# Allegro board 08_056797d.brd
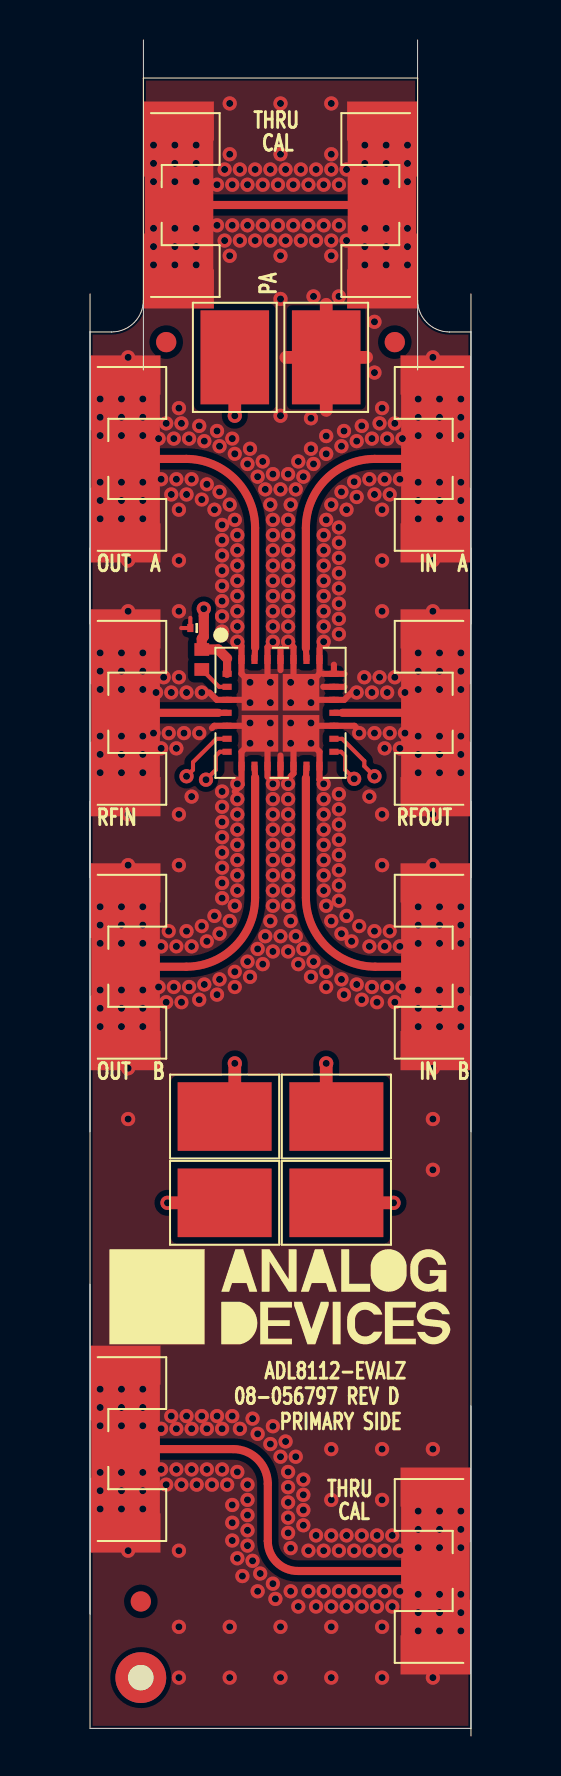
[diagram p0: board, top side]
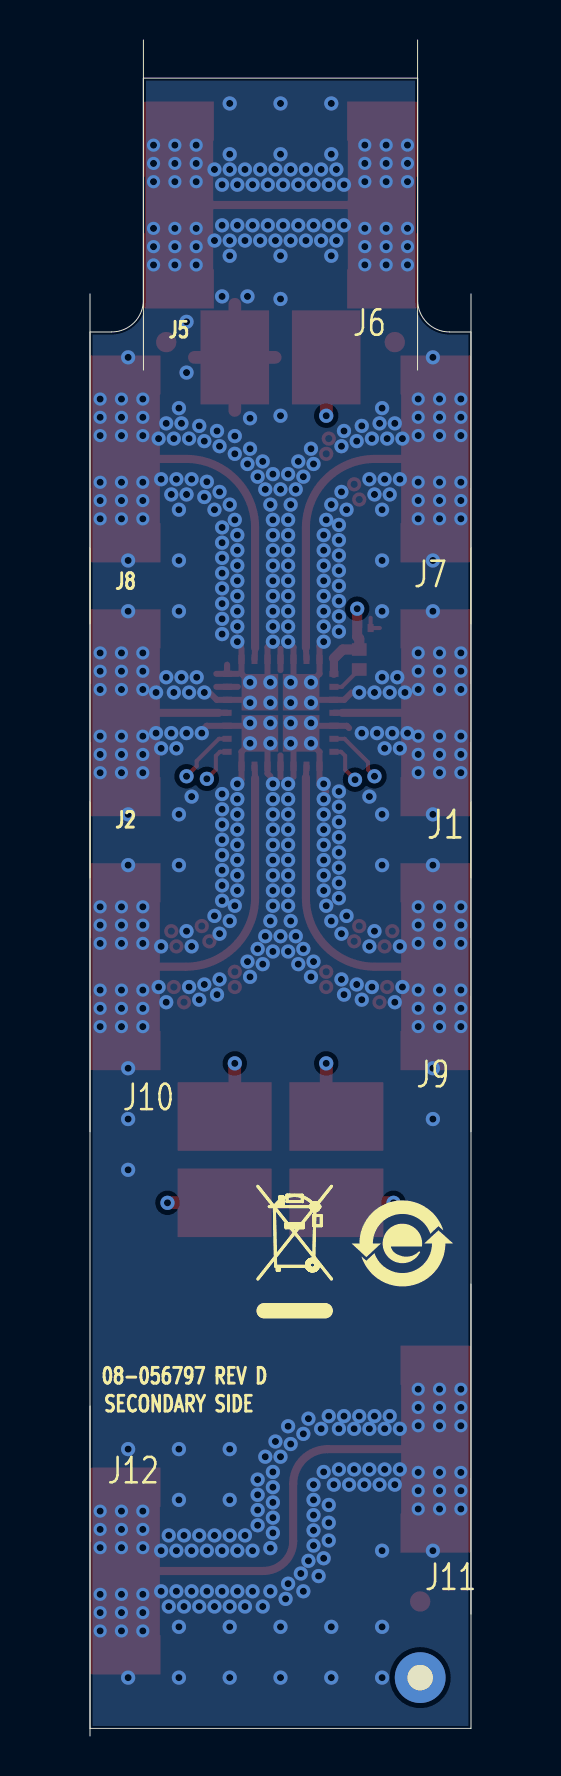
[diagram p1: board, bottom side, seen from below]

Outline 19.05 x 84.84 mm; copper layers: TOP, L2_GND, L3_GND, BOTTOM. Coordinates in mm from the lower left corner of the outline.
Outline path: 0,70.23 1.08,70.23 arc(2.2,70.7) 2.67,71.82 2.67,82.93 16.38,82.93 16.38,71.82 arc(16.85,70.7) 17.97,70.23 19.05,70.23 19.05,0.38 0,0.38 0,70.23

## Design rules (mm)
constraint set DEFAULT: min track width 0.203

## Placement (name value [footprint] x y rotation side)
C1  10pF  [C0201]  5.33 55.42 0 top
GND  5016  [CNKEY5016TP]  11.81 68.96 270 top
J1  25-146-1000-92  [CNK38G62THK_EDGE]  0 51.18 180 top
J2  25-146-1000-92  [CNK38G62THK_EDGE]  19.05 51.18 0 top
J5  25-146-1000-92  [CNK38G62THK_EDGE]  16.38 76.58 0 top
J6  25-146-1000-92  [CNK38G62THK_EDGE]  2.67 76.58 180 top
J7  25-146-1000-92  [CNK38G62THK_EDGE]  0 63.88 180 top
J8  25-146-1000-92  [CNK38G62THK_EDGE]  19.05 63.88 0 top
J9  25-146-1000-92  [CNK38G62THK_EDGE]  0 38.48 180 top
J10  25-146-1000-92  [CNK38G62THK_EDGE]  19.05 38.48 0 top
J11  25-146-1000-92  [CNK38G62THK_EDGE]  0 14.35 180 top
J12  25-146-1000-92  [CNK38G62THK_EDGE]  19.05 8.26 0 top
NOREF  -  []  0 0.38 0 top
NOREF#2  -  []  0 70.23 0 top
NOREF#3  -  []  19.05 0.38 90 top
NOREF#4  -  []  -148.69 242.57 0 top
NOREF#5  -  []  2.54 2.92 0 top
NOREF#6  -  []  16.38 82.93 0 top
NOREF#7  -  []  0 0.38 0 top
NOREF#8  -  []  9.53 21.97 0 top
NOREF#9  -  []  -226.7 -178.69 0 top
NOREF#10  -  []  0 70.23 0 top
NOREF#11  -  []  10.03 101.47 0 top
NOREF#12  -  []  2.67 82.93 270 top
NOREF#13  -  []  -104.65 -130.43 0 top
NOREF#14  -  []  16.38 82.93 180 top
NOREF#15  -  []  2.67 82.93 0 top
NOREF#16  -  []  0 51.18 0 top
NOREF#17  -  []  -229.87 -181.99 0 top
NOREF#18  -  []  19.05 0.38 0 top
NOREF#19  -  []  2.67 82.93 0 top
NOREF#20  -  [unnamed#2]  3.81 69.72 0 top
NOREF#21  -  []  19.05 0.38 90 top
NOREF#22  -  []  -88.9 -63.88 0 top
NOREF#23  -  []  0 0.38 0 top
NOREF#24  -  []  116.33 298.2 0 top
NOREF#25  -  []  -183.52 -64.13 0 top
NOREF#26  -  []  2.24 70.74 0 top
NOREF#27  -  []  19.05 0.38 90 top
NOREF#28  -  [unnamed#2]  15.24 69.72 0 top
NOREF#29  -  [unnamed#2]  2.54 2.92 0 top
NOREF#30  -  [unnamed#2]  2.54 6.73 0 top
NOREF#31  -  []  132.97 -25.02 0 top
NOREF#32  -  []  -2.29 167.26 0 top
NOREF#33  -  []  2.54 2.92 0 top
NOREF#34  -  []  9.02 20.95 180 bottom
NOREF#35  -  []  3.43 24.64 180 bottom
NOREF#36  -  []  9.53 57.15 90 bottom
R1  332  [R0402]  5.59 53.85 270 top
U1  ADL8112ACCZ  [LGA28_6X6_4PAD1_83X1_83]  9.53 51.18 270 top
VA  5016  [CNKEY5016TP]  6.73 26.67 0 top
VB  5016  [CNKEY5016TP]  6.73 30.99 0 top
VDD  5016  [CNKEY5016TP]  7.24 68.96 90 top
VDD_SW  5016  [CNKEY5016TP]  12.32 26.67 0 top
VSS  5016  [CNKEY5016TP]  12.32 30.99 0 top

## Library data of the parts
C1 = CAP: Tolerance: 5; User Part Number: UPN; alternate symbols: (C0201NC,C0201L); part number: CAP_SM-10PF,25V,5,E022849,C0201; tolerance: 5
GND VA VB VDD VDD_SW VSS = CNTP1P: Tolerance: N/A; User Part Number: UPN; alternate symbols: (); part number: CNTP1P_SM-5016,E005890,CNKEY5016TP; tolerance: N/A
J1 J2 J5-J12 = CNBNC4P: Tolerance: N/A; User Part Number: UPN; alternate symbols: (CNK38G62THK_EDGE_ADL81XX,CNK38G62THK_EDGE_HMC84X3,CNK40G62THK-SRI-SW_EDGE,CNK38G62THK_EDGE_ADMV1014); part number: CNBNC4P_SM-25-146-1000-92,E023346,CNK38G62THK_EDGE; tolerance: N/A
R1 = RES: User Part Number: UPN; Tolerance: 1; alternate symbols: (R0402L); part number: RES_SM-332,E056721,1/16W,1,R0402; tolerance: 1
U1 = ADL811X: User Part Number: UPN; Tolerance: N/A; alternate symbols: (); part number: ADL811X_SM-ADL8112ACCZ,E060217,LGA28_6X6_4PAD1_83X1_83; tolerance: N/A

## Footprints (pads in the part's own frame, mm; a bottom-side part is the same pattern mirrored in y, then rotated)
C0201
  rect 0.305x0.406 smd: 1(-0.318,0) 2(0.318,0)
CNK38G62THK_EDGE
  custom 0.102x0.102 smd: 1(-1.549,0)
  custom 0.873x0.873 smd: 2(-1.778,-3.302) 3(-1.778,3.302)
  rect 3.429x8.56 smd: 4(-1.778,0)
CNKEY5016TP
  rect 4.699x3.429 smd: 1(0,0)
LGA28_6X6_4PAD1_83X1_83
  rect 0.305x0.457 smd: 1(-1.95,-2.671) 2(-1.3,-2.671) 3(-0.65,-2.671) 4(0,-2.671) 5(0.65,-2.671) 6(1.3,-2.671) 7(1.95,-2.671) 15(1.95,2.671) 16(1.3,2.671) 17(0.65,2.671) 18(0,2.671) 19(-0.65,2.671) 20(-1.3,2.671) 21(-1.95,2.671)
  rect 0.457x0.305 smd: 8(2.671,-1.95) 9(2.671,-1.3) 10(2.671,-0.65) 11(2.671,0) 12(2.671,0.65) 13(2.671,1.3) 14(2.671,1.95) 22(-2.671,1.95) 23(-2.671,1.3) 24(-2.671,0.65) 25(-2.671,0) 26(-2.671,-0.65) 27(-2.671,-1.3) 28(-2.671,-1.95)
  rect 1.829x1.829 smd: PAD1(-1.028,-1.028) PAD2(1.028,-1.028) PAD3(1.028,1.028) PAD4(-1.028,1.028)
R0402
  rect 0.635x0.737 smd: 1(-0.5,0) 2(0.5,0)
unnamed#2
  round 1.016 smd: (0,0)

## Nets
GND: C1.1 GND.1(N1) J1.2 J1.3 J1.4(SH3) J2.2 J2.3 J2.4(SH3) J5.2 J5.3 J5.4(SH3) J6.2 J6.3 J6.4(SH3) J7.2 J7.3 J7.4(SH3) J8.2 J8.3 J8.4(SH3) J9.2 J9.3 J9.4(SH3) J10.2 J10.3 J10.4(SH3) J11.2 J11.3 J11.4(SH3) J12.2 J12.3 J12.4(SH3) U1.3 U1.5 U1.8 U1.10 U1.11 U1.12 U1.14 U1.17 U1.19 U1.20 U1.21 U1.22 U1.24 U1.25 U1.26 U1.28 U1.PAD1 U1.PAD2 U1.PAD3 U1.PAD4
VDD_PA: C1.2(N2) R1.1 U1.1 VDD.1(N1)
VDD_SW: U1.16 VDD_SW.1(N1)
VSS_SW: U1.15(VSS2) VSS.1(N1)
IN_A: J8.1 U1.23
IN_B: J10.1 U1.13
OUT_A: J7.1 U1.27
OUT_B: J9.1 U1.9
OUT_IN_B_THRU-CAL: J11.1 J12.1
RFIN: J1.1 U1.4
RFOUT: J2.1 U1.18
THRU-CAL: J5.1 J6.1
UNNAMED_4_ADL811X_I101_RBIAS: R1.2(N2) U1.2
VA: U1.6 VA.1(N1)
VB: U1.7 VB.1(N1)

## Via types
v1: diameter 0.711, hole 0.356, TOP to BOTTOM, 430 vias
v2: diameter 0.66, hole 0.356, TOP to BOTTOM, 180 vias
v3: diameter 0.711, hole 0.356, TOP to L2_GND, 20 vias

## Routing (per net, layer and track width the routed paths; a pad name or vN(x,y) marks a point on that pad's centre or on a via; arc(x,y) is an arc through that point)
GND: length 49.4
  TOP w0.203: 5.02,55.93 C1.1 4.56,55.42 ; 12.71,51.83 12.73,51.83
  TOP w0.254: 11.47,54.39 11.47,54.53 v1(11.68,54.74)
  TOP w0.305: v1(11.68,47.62) 11.47,47.83 U1.14 11.47,49.23 v1(11.05,49.66) U1.PAD3 ; U1.PAD4 10.93,51.83 U1.19 12.71,51.83 13.08,52.2 ; U1.PAD4 v1(11.05,52.7) 11.47,53.13 U1.22 11.47,54.39 ; U1.PAD4 10.17,52.59 U1.24 10.17,54.47 v1(9.91,54.74) ; U1.PAD1 8.88,52.59 U1.26 8.88,54.47 v1(9.14,54.74) ; U1.PAD1 8.12,51.83 U1.3 6.34,51.83 5.97,52.2 ; U1.PAD1 v1(8,52.7) 7.58,53.13 U1.28 7.58,54.53 v1(7.37,54.74) ; 13.59,50.16 13.22,50.53 U1.17 10.93,50.53 U1.PAD3 ; 6.1,50.42 6.21,50.53 U1.5 8.12,50.53 U1.PAD2 ; 8.88,47.98 U1.10 8.88,49.77 U1.PAD2 ; 9.53,53.32 U1.25 9.53,54.39 ; 9.53,49.04 U1.11 9.53,47.98 ; 12.73,52.48 U1.20 11.66,52.48 ; U1.21 12.2,53.59 ; U1.21 12.73,53.13 ; U1.21 11.66,53.13 ; U1.PAD2 v1(8,49.66) 7.58,49.23 U1.8 7.58,47.58 7.24,47.24 ; U1.PAD3 10.17,49.77 U1.12 10.17,48.15 10.03,48.01
  TOP w0.635: GND.1 11.81,71.62 ; GND.1 13.83,68.96 ; GND.1 11.81,66.31 ; GND.1 9.79,68.96
  vias: v1(1.91,68.96) v1(1.91,58.8) v1(1.91,56.26) v1(1.91,46.1) v1(1.91,43.56) v1(1.91,33.4) v1(1.91,30.86) v1(1.91,9.27) v1(3.18,50.16) v1(3.3,52.2) v1(3.43,64.9) v1(3.43,37.46) v1(3.56,62.87) v1(3.56,49.4) v1(3.56,39.5) v1(3.56,15.37) v1(3.56,13.34) v1(3.68,52.96) v1(3.81,65.66) v1(3.81,36.7) v1(3.81,12.57) v1(3.94,50.16) v1(4.06,62.1) v1(4.06,52.2) v1(4.06,16) v1(4.19,64.9) v1(4.32,62.87) v1(4.32,49.4) v1(4.32,15.37) v1(4.32,13.34) v1(4.45,66.42) v1(4.45,61.34) v1(4.45,58.8) v1(4.45,56.26) v1(4.45,52.96) v1(4.45,46.1) v1(4.45,43.56) v1(4.45,9.27) v1(4.45,5.46) v1(4.45,2.92) v1(4.57,65.66) v1(4.57,12.57) v1(4.7,50.16) v1(4.83,62.1) v1(4.83,52.2) v1(4.83,40.26) v1(4.83,16) v1(4.95,64.9) v1(4.95,37.46) v1(5.08,62.87) v1(5.08,46.99) v1(5.08,39.5) v1(5.08,15.37) v1(5.08,13.34) v1(5.33,12.57) v1(5.46,65.53) v1(5.46,50.16) v1(5.46,36.83) v1(5.59,52.2) v1(5.59,16) v1(5.72,64.77) v1(5.72,37.59) v1(5.84,15.37) v1(5.84,13.34) v1(6.1,12.57) v1(6.22,61.34) v1(6.22,41.02) v1(6.35,77.6) v1(6.35,75.57) v1(6.35,65.28) v1(6.35,37.08) v1(6.35,16) v1(6.48,64.52) v1(6.48,62.23) v1(6.48,40.13) v1(6.48,37.85) v1(6.6,60.58) v1(6.6,59.82) v1(6.6,59.05) v1(6.6,58.29) v1(6.6,57.53) v1(6.6,56.77) v1(6.6,56.01) v1(6.6,55.24) v1(6.6,47.24) v1(6.6,46.48) v1(6.6,45.72) v1(6.6,44.96) v1(6.6,44.2) v1(6.6,43.43) v1(6.6,42.67) v1(6.6,41.91) v1(6.6,15.37) v1(6.6,13.34) v1(6.73,78.36) v1(6.73,74.8) v1(6.86,12.57) v1(6.99,81.66) v1(6.99,79.12) v1(6.99,74.04) v1(6.99,61.59) v1(6.99,40.77) v1(6.99,5.46) v1(6.99,2.92) v1(7.11,77.6) v1(7.11,75.57) v1(7.11,16) v1(7.11,11.56) v1(7.11,10.67) v1(7.11,9.78) v1(7.24,60.83) v1(7.24,41.53) v1(7.37,60.07) v1(7.37,59.31) v1(7.37,58.55) v1(7.37,57.78) v1(7.37,57.02) v1(7.37,56.26) v1(7.37,55.5) v1(7.37,47.62) v1(7.37,46.86) v1(7.37,46.1) v1(7.37,45.34) v1(7.37,44.58) v1(7.37,43.81) v1(7.37,43.05) v1(7.37,42.29) v1(7.37,13.21) v1(7.37,8.89) v1(7.49,78.36) v1(7.49,74.8) v1(7.49,15.37) v1(7.62,8) v1(7.87,77.6) v1(7.87,75.57) v1(7.87,63.63) v1(7.87,38.73) v1(7.87,12.57) v1(7.87,11.81) v1(7.87,11.05) v1(7.87,10.29) v1(7.87,9.53) v1(8,64.39) v1(8,51.69) v1(8,50.67) v1(8,37.97) v1(8.13,15.88) v1(8.13,8.76) v1(8.26,78.36) v1(8.26,74.8) v1(8.38,62.99) v1(8.38,39.37) v1(8.38,15.11) v1(8.38,7.24) v1(8.51,8.13) v1(8.64,77.6) v1(8.64,75.57) v1(8.64,63.75) v1(8.64,38.61) v1(8.76,62.36) v1(8.76,40.01) v1(9.02,78.36) v1(9.02,74.8) v1(9.02,61.59) v1(9.02,52.7) v1(9.02,51.69) v1(9.02,50.67) v1(9.02,49.66) v1(9.02,40.77) v1(9.02,14.61) v1(9.14,63.12) v1(9.14,60.83) v1(9.14,60.07) v1(9.14,59.31) v1(9.14,58.55) v1(9.14,57.78) v1(9.14,57.02) v1(9.14,56.26) v1(9.14,55.5) v1(9.14,47.62) v1(9.14,46.86) v1(9.14,46.1) v1(9.14,45.34) v1(9.14,44.58) v1(9.14,43.81) v1(9.14,43.05) v1(9.14,42.29) v1(9.14,41.53) v1(9.14,39.24) v1(9.14,15.49) v1(9.14,7.62) v1(9.27,6.86) v1(9.4,77.6) v1(9.4,75.57) v1(9.53,81.66) v1(9.53,79.12) v1(9.53,74.04) v1(9.53,71.88) v1(9.53,66.04) v1(9.53,62.36) v1(9.53,40.01) v1(9.53,13.97) v1(9.53,5.46) v1(9.53,2.92) v1(9.78,78.36) v1(9.78,74.8) v1(9.78,14.73) v1(9.91,63.12) v1(9.91,60.83) v1(9.91,60.07) v1(9.91,59.31) v1(9.91,58.55) v1(9.91,57.78) v1(9.91,57.02) v1(9.91,56.26) v1(9.91,55.5) v1(9.91,47.62) v1(9.91,46.86) v1(9.91,46.1) v1(9.91,45.34) v1(9.91,44.58) v1(9.91,43.81) v1(9.91,43.05) v1(9.91,42.29) v1(9.91,41.53) v1(9.91,39.24) v1(9.91,13.21) v1(9.91,12.45) v1(9.91,11.68) v1(9.91,10.92) v1(9.91,10.16) v1(10.03,61.59) v1(10.03,52.7) v1(10.03,51.69) v1(10.03,50.67) v1(10.03,49.66) v1(10.03,40.77) v1(10.03,9.4) v1(10.03,7.24) v1(10.16,77.6) v1(10.16,75.57) v1(10.29,62.36) v1(10.29,40.01) v1(10.29,13.97) v1(10.41,63.75) v1(10.41,38.61) v1(10.41,6.48) v1(10.54,78.36) v1(10.54,74.8) v1(10.67,62.99) v1(10.67,39.37) v1(10.67,12.83) v1(10.67,12.07) v1(10.67,11.3) v1(10.67,10.54) v1(10.92,77.6) v1(10.92,75.57) v1(10.92,9.27) v1(10.92,7.24) v1(11.05,65.91) v1(11.05,64.39) v1(11.05,51.69) v1(11.05,50.67) v1(11.05,37.97) v1(11.18,72.01) v1(11.18,63.63) v1(11.18,38.73) v1(11.3,78.36) v1(11.3,74.8) v1(11.3,10.03) v1(11.3,6.48) v1(11.68,77.6) v1(11.68,75.57) v1(11.68,60.07) v1(11.68,59.31) v1(11.68,58.55) v1(11.68,57.78) v1(11.68,57.02) v1(11.68,56.26) v1(11.68,55.5) v1(11.68,46.86) v1(11.68,46.1) v1(11.68,45.34) v1(11.68,44.58) v1(11.68,43.81) v1(11.68,43.05) v1(11.68,42.29) v1(11.68,9.27) v1(11.68,7.24) v1(11.81,65.02) v1(11.81,64.14) v1(11.81,60.83) v1(11.81,41.53) v1(12.07,81.66) v1(12.07,79.12) v1(12.07,78.36) v1(12.07,74.8) v1(12.07,74.04) v1(12.07,61.59) v1(12.07,40.77) v1(12.07,14.35) v1(12.07,11.81) v1(12.07,10.03) v1(12.07,6.48) v1(12.07,5.46) v1(12.07,2.92) v1(12.45,77.6) v1(12.45,75.57) v1(12.45,72.01) v1(12.45,60.45) v1(12.45,59.69) v1(12.45,58.93) v1(12.45,58.17) v1(12.45,57.4) v1(12.45,56.64) v1(12.45,55.88) v1(12.45,55.12) v1(12.45,47.12) v1(12.45,46.35) v1(12.45,45.59) v1(12.45,44.83) v1(12.45,44.07) v1(12.45,43.31) v1(12.45,42.55) v1(12.45,41.78) v1(12.45,9.27) v1(12.45,7.24) v1(12.57,64.52) v1(12.57,62.23) v1(12.57,40.13) v1(12.57,37.85) v1(12.7,65.28) v1(12.7,37.08) v1(12.83,78.36) v1(12.83,74.8) v1(12.83,61.34) v1(12.83,41.02) v1(12.83,10.03) v1(12.83,6.48) v1(13.21,62.74) v1(13.21,9.27) v1(13.21,7.24) v1(13.34,64.77) v1(13.34,61.98) v1(13.34,52.2) v1(13.34,37.59) v1(13.46,50.16) v1(13.59,65.53) v1(13.59,36.83) v1(13.59,10.03) v1(13.59,6.48) v1(13.72,52.96) v1(13.97,62.87) v1(13.97,46.99) v1(13.97,39.5) v1(13.97,9.27) v1(13.97,7.24) v1(14.1,64.9) v1(14.1,52.2) v1(14.1,37.46) v1(14.22,70.74) v1(14.22,68.2) v1(14.22,62.1) v1(14.22,50.16) v1(14.22,40.26) v1(14.35,10.03) v1(14.35,6.48) v1(14.48,65.66) v1(14.48,52.96) v1(14.61,66.42) v1(14.61,61.34) v1(14.61,58.8) v1(14.61,56.26) v1(14.61,46.1) v1(14.61,43.56) v1(14.61,14.35) v1(14.61,11.81) v1(14.61,5.46) v1(14.61,2.92) v1(14.73,62.87) v1(14.73,49.4) v1(14.73,9.27) v1(14.73,7.24) v1(14.86,64.9) v1(14.86,52.2) v1(14.99,62.1) v1(14.99,50.16) v1(15.11,10.03) v1(15.11,6.48) v1(15.24,65.66) v1(15.24,52.96) v1(15.24,36.7) v1(15.49,62.87) v1(15.49,49.4) v1(15.49,39.5) v1(15.49,9.27) v1(15.49,7.24) v1(15.62,64.9) v1(15.62,37.46) v1(15.75,52.2) v1(15.75,50.16) v1(17.15,68.96) v1(17.15,58.8) v1(17.15,56.26) v1(17.15,46.1) v1(17.15,43.56) v1(17.15,33.4) v1(17.15,30.86) v1(17.15,28.32) v1(17.15,14.35) v1(17.15,2.92) v2(0.51,66.88) v2(0.51,65.96) v2(0.51,65.05) v2(0.51,62.72) v2(0.51,61.8) v2(0.51,60.89) v2(0.51,54.18) v2(0.51,53.26) v2(0.51,52.35) v2(0.51,50.02) v2(0.51,49.1) v2(0.51,48.19) v2(0.51,41.48) v2(0.51,40.56) v2(0.51,39.65) v2(0.51,37.32) v2(0.51,36.4) v2(0.51,35.49) v2(0.51,17.35) v2(0.51,16.43) v2(0.51,15.52) v2(0.51,13.19) v2(0.51,12.27) v2(0.51,11.36) v2(1.57,66.88) v2(1.57,65.96) v2(1.57,65.05) v2(1.57,62.72) v2(1.57,61.8) v2(1.57,60.89) v2(1.57,54.18) v2(1.57,53.26) v2(1.57,52.35) v2(1.57,50.02) v2(1.57,49.1) v2(1.57,48.19) v2(1.57,41.48) v2(1.57,40.56) v2(1.57,39.65) v2(1.57,37.32) v2(1.57,36.4) v2(1.57,35.49) v2(1.57,17.35) v2(1.57,16.43) v2(1.57,15.52) v2(1.57,13.19) v2(1.57,12.27) v2(1.57,11.36) v2(2.64,66.88) v2(2.64,65.96) v2(2.64,65.05) v2(2.64,62.72) v2(2.64,61.8) v2(2.64,60.89) v2(2.64,54.18) v2(2.64,53.26) v2(2.64,52.35) v2(2.64,50.02) v2(2.64,49.1) v2(2.64,48.19) v2(2.64,41.48) v2(2.64,40.56) v2(2.64,39.65) v2(2.64,37.32) v2(2.64,36.4) v2(2.64,35.49) v2(2.64,17.35) v2(2.64,16.43) v2(2.64,15.52) v2(2.64,13.19) v2(2.64,12.27) v2(2.64,11.36) v2(3.18,79.58) v2(3.18,78.66) v2(3.18,77.75) v2(3.18,75.42) v2(3.18,74.5) v2(3.18,73.59) v2(4.24,79.58) v2(4.24,78.66) v2(4.24,77.75) v2(4.24,75.42) v2(4.24,74.5) v2(4.24,73.59) v2(5.31,79.58) v2(5.31,78.66) v2(5.31,77.75) v2(5.31,75.42) v2(5.31,74.5) v2(5.31,73.59) v2(13.74,79.58) v2(13.74,78.66) v2(13.74,77.75) v2(13.74,75.41) v2(13.74,74.5) v2(13.74,73.58) v2(14.81,79.58) v2(14.81,78.66) v2(14.81,77.75) v2(14.81,75.41) v2(14.81,74.5) v2(14.81,73.58) v2(15.88,79.58) v2(15.88,78.66) v2(15.88,77.75) v2(15.88,75.41) v2(15.88,74.5) v2(15.88,73.58) v2(16.41,66.88) v2(16.41,65.96) v2(16.41,65.05) v2(16.41,62.71) v2(16.41,61.8) v2(16.41,60.88) v2(16.41,54.18) v2(16.41,53.26) v2(16.41,52.35) v2(16.41,50.01) v2(16.41,49.1) v2(16.41,48.18) v2(16.41,41.48) v2(16.41,40.56) v2(16.41,39.65) v2(16.41,37.31) v2(16.41,36.4) v2(16.41,35.48) v2(16.41,11.25) v2(16.41,10.34) v2(16.41,9.42) v2(16.41,7.09) v2(16.41,6.17) v2(16.41,5.26) v2(17.48,66.88) v2(17.48,65.96) v2(17.48,65.05) v2(17.48,62.71) v2(17.48,61.8) v2(17.48,60.88) v2(17.48,54.18) v2(17.48,53.26) v2(17.48,52.35) v2(17.48,50.01) v2(17.48,49.1) v2(17.48,48.18) v2(17.48,41.48) v2(17.48,40.56) v2(17.48,39.65) v2(17.48,37.31) v2(17.48,36.4) v2(17.48,35.48) v2(17.48,11.25) v2(17.48,10.34) v2(17.48,9.42) v2(17.48,7.09) v2(17.48,6.17) v2(17.48,5.26) v2(18.54,66.88) v2(18.54,65.96) v2(18.54,65.05) v2(18.54,62.71) v2(18.54,61.8) v2(18.54,60.88) v2(18.54,54.18) v2(18.54,53.26) v2(18.54,52.35) v2(18.54,50.01) v2(18.54,49.1) v2(18.54,48.18) v2(18.54,41.48) v2(18.54,40.56) v2(18.54,39.65) v2(18.54,37.31) v2(18.54,36.4) v2(18.54,35.48) v2(18.54,11.25) v2(18.54,10.34) v2(18.54,9.42) v2(18.54,7.09) v2(18.54,6.17) v2(18.54,5.26) v3(3.94,40.26) v3(4.19,37.46) v3(4.32,39.5) v3(4.57,36.7) v3(5.59,61.85) v3(5.59,40.51) v3(5.84,62.61) v3(5.84,39.75) v3(7.11,64.9) v3(7.24,64.14) v3(7.24,38.23) v3(7.24,37.46) v3(11.81,38.23) v3(11.81,37.46) v3(13.08,39.75) v3(13.46,40.51) v3(14.35,36.7) v3(14.73,39.5) v3(14.86,37.46) v3(14.99,40.26)
VDD_PA: length 18.5
  TOP w0.406: U1.1 6.85,53.9 ; 5.69,56.05 5.65,56.01 C1.2
  TOP w0.508: 6.85,53.9 6.41,54.35 R1.1 5.59,54.89 5.69,54.99 v1(5.69,56.39)
  TOP w0.635: VDD.1 v1(7.24,66.04)
  L3_GND w0.203: v1(5.69,56.39) 5.69,60.6 5.33,60.96 5.33,61.59 5.72,61.98 5.72,62.61 7.24,64.14 v1(7.24,66.04)
VDD_SW: length 28.3
  TOP w0.203: v1(14.22,48.01) 13.72,48.51 13.72,48.77 12.6,49.88 U1.16
  TOP w0.635: v1(15.18,26.67) VDD_SW.1
  L3_GND w0.203: v1(14.22,48.01) 15.37,46.86 15.37,40.39 14.83,39.85 14.83,37.31 14.48,36.96 14.48,33.53 15.18,32.83 v1(15.18,26.67)
VSS_SW: length 20
  TOP w0.203: U1.15 12.55,49.23 12.76,49.03 12.76,48.33 v1(13.21,47.88)
  TOP w0.635: v1(11.81,33.65) 11.81,31.5 VSS.1
  L3_GND w0.203: v1(13.21,47.88) 13.21,41.91 13.59,41.53 13.59,40.13 13.21,39.75 13.21,39.5 11.81,38.1 v1(11.81,33.65)
IN_A: length 15.3
  TOP w0.305: U1.23 10.8,54.41
  TOP w0.406: J8.1 14.24,63.88 arc(11.8,62.87) 10.8,60.43 10.8,54.41
IN_B: length 15.2
  TOP w0.305: U1.13 10.8,47.92
  TOP w0.406: J10.1 14.26,38.48 arc(11.81,39.5) 10.8,41.95 10.8,47.92
OUT_A: length 15.3
  TOP w0.305: U1.27 8.26,54.44
  TOP w0.406: J7.1 4.8,63.88 arc(7.24,62.87) 8.26,60.43 8.26,54.44
OUT_B: length 15.3
  TOP w0.305: U1.9 8.26,47.95
  TOP w0.406: J9.1 4.81,38.48 arc(7.25,39.49) 8.26,41.93 8.26,47.95
OUT_IN_B_THRU-CAL: length 20.7
  TOP w0.406: J12.1 10.39,8.26 arc(9.33,8.69) 8.89,9.75 8.89,12.62 arc(8.38,13.84) 7.16,14.35 J11.1
RFIN: length 5.3
  TOP w0.305: U1.4 6.43,51.18
  TOP w0.406: 6.43,51.18 J1.1
RFOUT: length 5.3
  TOP w0.305: U1.18 12.62,51.18
  TOP w0.406: 12.62,51.18 J2.1
THRU-CAL: length 10.6
  TOP w0.406: J5.1 J6.1
UNNAMED_4_ADL811X_I101_RBIAS: length 1.6
  TOP w0.203: U1.2 6.45,52.48 R1.2
VA: length 28.5
  TOP w0.203: v1(4.83,48.01) 5.15,48.33 5.15,48.71 6.32,49.88 U1.6
  TOP w0.635: v1(3.87,26.67) VA.1
  L3_GND w0.203: v1(4.83,48.01) 3.68,46.86 3.68,40.39 4.19,39.88 4.19,37.34 4.7,36.83 4.7,33.66 3.87,32.83 v1(3.87,26.67)
VB: length 20
  TOP w0.203: U1.7 6.5,49.23 6.29,49.03 6.29,48.33 v1(5.8,47.84)
  TOP w0.635: VB.1 7.24,31.5 v1(7.24,33.65)
  L3_GND w0.203: v1(7.24,33.65) 7.24,38.1 5.84,39.5 5.84,39.75 5.46,40.13 5.46,41.53 5.8,41.87 v1(5.8,47.84)

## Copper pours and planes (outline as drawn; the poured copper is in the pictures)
GND on TOP: 2.79,82.8 16.26,82.8 16.26,71.82 16.76,70.61 17.97,70.1 18.92,70.1 18.92,0.51 0.13,0.51 0.13,70.1 1.08,70.1 2.29,70.61 2.79,71.82 ; 1 cut-out
GND on BOTTOM: 18.92,70.1 18.92,0.51 0.13,0.51 0.13,70.1 1.08,70.1 2.29,70.61 2.79,71.82 2.79,82.8 16.26,82.8 16.26,71.82 16.76,70.61 17.97,70.1
GND on L2_GND, L3_GND: 18.92,70.1 18.92,68.2 19.05,68.2 19.05,59.56 18.92,59.56 18.92,55.5 19.05,55.5 19.05,46.86 18.92,46.86 18.92,42.8 19.05,42.8 19.05,34.16 18.92,34.16 18.92,24 19.05,24 19.05,15.24 18.92,15.24 18.92,0.51 0.13,0.51 0.13,21.46 0,21.46 0,30.1 0.13,30.1 0.13,34.16 0,34.16 0,42.8 0.13,42.8 0.13,46.86 0,46.86 0,55.5 0.13,55.5 0.13,59.56 0,59.56 0,68.2 0.13,68.2 0.13,70.1 1.08,70.1 2.29,70.61 2.79,71.82 2.79,72.26 2.67,72.26 2.67,80.9 2.79,80.9 2.79,82.8 16.26,82.8 16.26,80.9 16.38,80.9 16.38,72.26 16.26,72.26 16.26,71.82 16.76,70.61 17.97,70.1

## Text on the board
Ref Des/Silkscreen Bottom: SECONDARY SIDE | 08-056797 REV D
Ref Des/Silkscreen Top: OUT | RFIN | A | B | 08-056797 REV D | THRU | CAL | ADL8112-EVALZ | PRIMARY SIDE | RFOUT | IN | PA
DIMENSION: PREPREG A/R | 370HR A/R | BOARD EDGE IN THE PLATED AND NON-PLATED AREA | MUST BE FLAT/FLUSH. NO BUMPS. | SEE DETAIL B AND NOTE 17 | 0.042", +/-0.002" NON-PLATED DIMENSION | 10 PLACES | " " | (REF) | DIA MAX | SEE NOTE 16
PAGE_OUTLINE: ANALOG DEVICES | 600-01711-00-1 | B | C | D | CHANGE PER ECR# 086866 | CHANGE PER ECR# 089632 | CHANGE PER ECR# 112205 | 17APR19 | 11OCT19 | 16JAN23 | H. NGUYEN | C. NELVIS
DISPLAY_TOP: ENIG (Electroless Nickel/Immersion Gold) | PER IPC-4552 LATEST REVISION | SECONDARY SOLDER MASK | SECONDARY SILKSCREEN | 15.    CRITICAL LINE WIDTH (CPWG) = 16 MILS +/- 1 MIL. | ADJUST PROCESS TO ACHIEVE WIDTH. | 16.    DESIGNATED DRILL TO BE CONDUCTIVE EPOXY FILLED AND | CO-PLANNAR PRIOR TO OVER-PLATING. | 17.    EDGE PLATING TO CONNECT OUTER AND INTERNAL GROUND LAYERS FOR THE | WIDTH OF THE CONNECTORS. | CRITICAL LINE GAP (CPWG) = 13 MILS +/- 1 MIL. | ROGERS 4350B 10 MIL
User.14: L2 GROUND | 08-      -07
User.15: L3 GROUND | 08-      -08
User.16: BLIND VIAS | LAYER 1 TO LAYER 2 | MAX DIA
User.21: BLIND VIAS LAYERS 1-2 | SEE NOTE 16
User.23: HUGO NGUYEN | 24JAN19 | CHANGE PER ECR# 086866 | CHANGE PER ECR# 089632 | CHANGE PER ECR# 112205 | B | C | D | 17APR19 | 11OCT19 | 16JAN23 | H. NGUYEN | C. NELVIS | ADL8112 CUSTOMER EVAL Z
User.31: FIGURE | SIZE | 14.0 | PLATED | DRILL CHART: TOP to L2_GND | ALL UNITS ARE IN MILS | QTY | 20 | TOLERANCE/NOTES
User.34: FIGURE | SIZE | 14.0 | 50.0 | PLATED | NON-PLATED | DRILL CHART: TOP to BOTTOM | ALL UNITS ARE IN MILS | QTY | 610 | 1 | TOLERANCE/NOTES
